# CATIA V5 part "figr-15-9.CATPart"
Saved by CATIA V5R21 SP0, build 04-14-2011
Part number: Part1
Bounding box of the stored display mesh (mm): x -50 to 50, y -32.5 to 33.5, z -52 to 1
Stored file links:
  D:\CATIA V5R21 E-RESOURCES\CATIA-V5R21\catia-v5r21-prt\c15-catia-v5r20-prt\c15-catia-v5r21-figr-15-9.CATPart
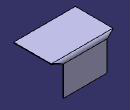
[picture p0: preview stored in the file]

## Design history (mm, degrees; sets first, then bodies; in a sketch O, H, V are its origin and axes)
SheetMetalParameters1: Thickness 1, BendRadius 4, KFactor 0.475772 {= log(min(100,max(20*SheetMetalParameters1.BendRadius,SheetMetalParameters1.Thickness)/SheetMetalParameters1.Thickness))/log(100)/2}, ReliefRadialLength 4, ReliefAxialLength 4, MinimumBendRadius 0
Body1 (main body)
  Sketch1 on xy-plane, origin (0, 0, 0), H (1, 0, 0), V (0, 1, 0)
    line L1 (-50, 32.5) -> (50, 32.5)
    line L2 (50, 32.5) -> (50, -32.5)
    line L3 (50, -32.5) -> (-50, -32.5)
    line L4 (-50, -32.5) -> (-50, 32.5)
    length L1 = 100
    length L2 = 65
    horizontal: L1 H, L3 H
    vertical: L2 V, L4 V
    symmetry: L4 L2 V, L1 L3 H
  Wall1: Thickness 1, Profile Sketch1
  d_NewWallOnEdge1: NewWallOnEdge_Edge edge [face of Wall1 | face of Wall1], NewWallOnEdge_Length 53, NewWallOnEdge_HeightLimitOffset 0, NewWallOnEdge_WidthOffset1 -15, NewWallOnEdge_WidthOffset2 -15, NewWallOnEdge_Angle 90, NewWallOnEdge_BendRadiusValue 4 {= SheetMetalParameters1.BendRadius}, NewWallOnEdge_BendTable SheetMetalParameters1, KFacteur 0.475772 {= log(min(100,max(20*d_NewWallOnEdge1.Radius,SheetMetalParameters1.Thickness)/SheetMetalParameters1.Thickness))/log(100)/2}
